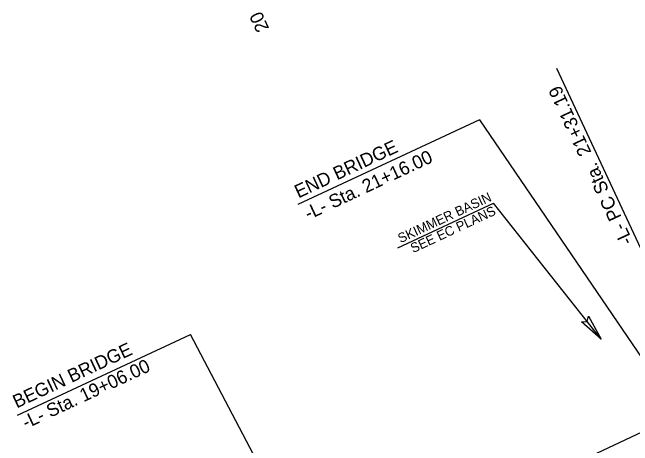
# Model space of a CAD drawing. Extents: x 2320644 to 2322941, y 921672 to 923041.
# Drawn here: x 2321430.4 to 2321755.6, y 922253.9 to 922481.1 of the extents above; entities that cross this region are included whole.
import ezdxf

# ---------------------------------------------------------------- set-up
doc = ezdxf.new("R2010")
doc.units = 0
for name, color, linetype in [('Prop Dimension', 7, 'Continuous'), ('Prop Horizontal Alignment Tick Large', 7, 'Continuous'), ('Prop North Arrow NAD83 for Plan Sheets CELL', 7, 'Continuous'), ('Prop Terminator CELL', 7, 'Continuous'), ('Sheet Sticker Exception Certification CELL', 7, 'Continuous')]:
    doc.layers.add(name, color=color, linetype=linetype)

msp = doc.modelspace()

# ---------------------------------------------------------------- linework, layer by layer
at = {"layer": 'Prop Dimension'}
msp.add_line((2321803.76, 922263.03), (2321715.85, 922451.63), dxfattribs=at)
at = {"layer": 'Prop Horizontal Alignment Tick Large'}
msp.add_line((2321592.68, 922182.85), (2321783.02, 922271.57), dxfattribs=at)
at = {"layer": 'Prop North Arrow NAD83 for Plan Sheets CELL'}
for p, q in [((2321675.27, 922424.8), (2321580.05, 922380.36)), ((2321675.27, 922424.8), (2321790.63, 922255.25)), ((2321632.46, 922357.6), (2321682.66, 922381)), ((2321739.05, 922309.73), (2321682.66, 922381)), ((2321433.05, 922269.79), (2321523.79, 922312.14)), ((2321600.29, 922166.53), (2321523.79, 922312.14))]:
    msp.add_line(p, q, dxfattribs=at)
at = {"layer": 'Sheet Sticker Exception Certification CELL'}
msp.add_lwpolyline([(2321732.5, 922321.76), (2321739.05, 922309.73), (2321728.75, 922318.88), (2321731.7, 922319.02)], close=True, dxfattribs=at)

# ---------------------------------------------------------------- texts
at = {"layer": 'Prop Dimension'}
msp.add_text('-L- PC Sta.  21+31.19', height=7, rotation=114.9913, dxfattribs=at).set_placement((2321755.88, 922361.02))
at = {"layer": 'Prop North Arrow NAD83 for Plan Sheets CELL'}
for s, height, rotation, p in [('END BRIDGE', 7, 25.0187, (2321580.36, 922383.51)), ('-L- Sta. 21+16.00 ', 7, 25.0187, (2321585.61, 922372.13)), ('SKIMMER BASIN', 5, 24.9913, (2321633.93, 922360.01)), ('SEE EC PLANS', 5, 24.9913, (2321640.55, 922354.83)), ('BEGIN BRIDGE', 7, 25.0187, (2321432.65, 922273.35)), ('-L- Sta. 19+06.00 ', 7, 25.0187, (2321437.53, 922262.54))]:
    msp.add_text(s, height=height, rotation=rotation, dxfattribs=at).set_placement(p)
at = {"layer": 'Prop Terminator CELL'}
msp.add_text('20', height=7, rotation=114.9913, dxfattribs=at).set_placement((2321565.14, 922472.73))

doc.saveas('drawing.dxf')
